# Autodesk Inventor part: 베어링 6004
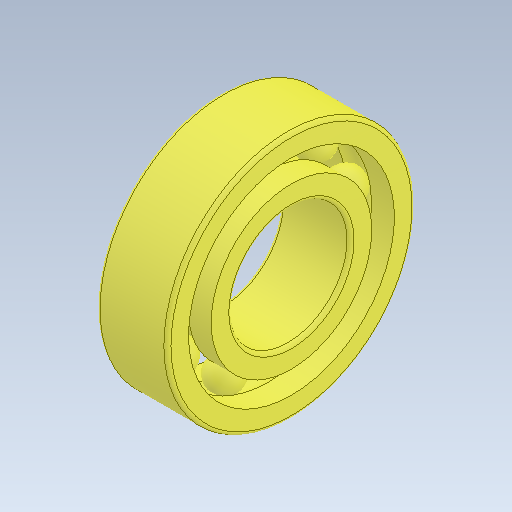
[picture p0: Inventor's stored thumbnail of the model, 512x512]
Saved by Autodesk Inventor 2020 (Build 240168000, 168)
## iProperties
Created: 2024-04
Part Number: 베어링 6004
Material: 강철, 연강
Description: 깊은 그루브 볼 베어링
Document SubType Name: Modeling
Designer: oem
Density: 7.85 g/cm^3
Appearance: 기본값
Mass: 68.2267 g
Surface Area: 70.0178 cm^2
Volume: 8.6913 cm^3
Sending System: Autodesk Inventor 2025
Preprocessor: ST-DEVELOPER v20
Author: jhkim
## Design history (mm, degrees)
feature "Solid1"
feature "Solid1:1"
feature "Solid1:2"
feature "Solid1:3"
feature "Solid1:4"
feature "Solid1:5"
feature "Solid1:6"
feature "Solid1:7"
feature "Solid1:8"
feature "Solid1:9"
feature "Solid1:10"
node "솔리드1"
node "솔리드2"
node "솔리드3"
node "솔리드4"
node "솔리드5"
node "솔리드6"
node "솔리드7"
node "솔리드8"
node "솔리드9"
node "솔리드10"
node "솔리드11"
